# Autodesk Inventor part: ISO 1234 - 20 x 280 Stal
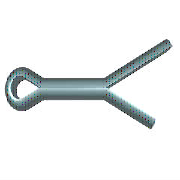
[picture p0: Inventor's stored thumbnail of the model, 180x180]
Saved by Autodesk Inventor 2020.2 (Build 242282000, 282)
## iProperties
Manager: www.cadconsulting.pl
Company: Fabian Stasiak CAD Consulting
IsCustomPart: 0
Created: 2010-10
Part Number: ISO 1234 - 20 x 280 Stal
Material: Stal
Description: Zawleczka
Document SubType Name: Modeling
Standard: ISO 1234
Designer: F.Stasiak
Standard Revision: Druga edycja 1997-11-01
Standards Organization: ISO
Language: pl-PL
Size Designation: 20 x 280
Categories: <MemberInstance><Categories><Category DisplayName="Mocowania" InternalName="e4da775c-781d-43d5-af7c-5136215cf5a6" Mnemonic="FSTN"><Category DisplayName="Kołki"
Density: 7.85 g/cm^3
Appearance: Metal-Stal
Author: F.Stasiak
Subject: Zbiór ćwiczeń. Autodesk Inventor 2020. Kurs podstawowy
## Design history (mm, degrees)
sketch "Szkic1"
  geometry: L1 (0, 9.65)-(248, 9.65); L2 (0, -9.65)-(248, -9.65); L3 (248, 9.65)-(280, 21.91); L4 (280, 21.91)-(283.224, 13.495); L5 (283.224, 13.495)-(248, 0); L6 (248, 0)-(289.524, -15.909); L7 (289.524, -15.909)-(286.3, -24.323); L8 (286.3, -24.323)-(248, -9.65); L9 (0, 0)-(-16.309, -8.511); L10 (0, 0)-(-16.309, 8.511); L11 (0, 9.65)-(0, -9.65); L12 (0, 9.65)-(-10.457, 16.267); L13 (0, -9.65)-(-10.457, -16.267); L14 (-40, 0)-(248, 0); L15 (248, 9.65)-(248, -9.65); A1 r 19.25 centre (-20.75, 0) between (-10.457, 16.267) and (-10.457, -16.267); A2 r 9.6 centre (-20.75, 0) between (-16.309, 8.511) and (-16.309, -8.511); 1 further point
  constraints: 30 end point, 5 point on circle, 4 parallel, 4 perpendicular, 4 point on line, 4 tangent, 2 centre point, 2 midpoint, 1 coincident, 1 horizontal
  dimensions: "d0" = 248 distance of L1.start L1.end (= MSIAB); "d1" = 280 horizontal distance of L1.start L3.end (= SNLG); "d2" = 159.037 deg angle of L1 L3; "d3" = 159.037 deg angle of L2 L8; "d4" = 6.3 horizontal distance of L3.end L7.end (= LGDIF); "d5" = 9.6 radius of A2 (= -0.5 x SNND1 + 0.5 x KBR); "d6" = 19.25 radius of A1 (= 0.5 x KBR); "d7" = 9.65 distance from line of L1 L9.start (= 0.5 x SNND1); "d8" = 9.65 distance between parallel lines of L2 L14 (= 0.5 x SNND1); "d9" = 20.75 distance from line of L11 A1.centre (= KOL - 0.5 x KBR)
extrude "Bryła" new body sketch "Szkic1" stored distance "d10" = 19.3 (= SNND1); taper "d11" = 0 deg
workaxis "Work Axis1"
workplane "Work Plane1"
workplane "Work Plane3"
body "Solid1"
fillet "Zaokrąglenie" dims "d12" = 6.755 (= 0.35 x SNND1)
other parameters: "SNLG" = 280 [user parameter; used in 1 equation term], "SNND1" = 19.3 [user parameter; used in 5 equation terms], "KBR" = 38.5 [user parameter; used in 3 equation terms], "LGDIF" = 6.3 [user parameter; used in 1 equation term], "MSIAB" = 248 [user parameter; used in 1 equation term], "d15" = 0, "d16" = 0, "d17" = 0, "DSH" = 26 [user parameter]
